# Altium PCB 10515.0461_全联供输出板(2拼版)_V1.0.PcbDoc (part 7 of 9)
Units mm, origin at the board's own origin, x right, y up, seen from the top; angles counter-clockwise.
Board outline 283.88 x 134.8 mm, 2 copper layers (Top Layer, Bottom Layer); 298 components, 0 nets, 1264 pads, 970 vias.
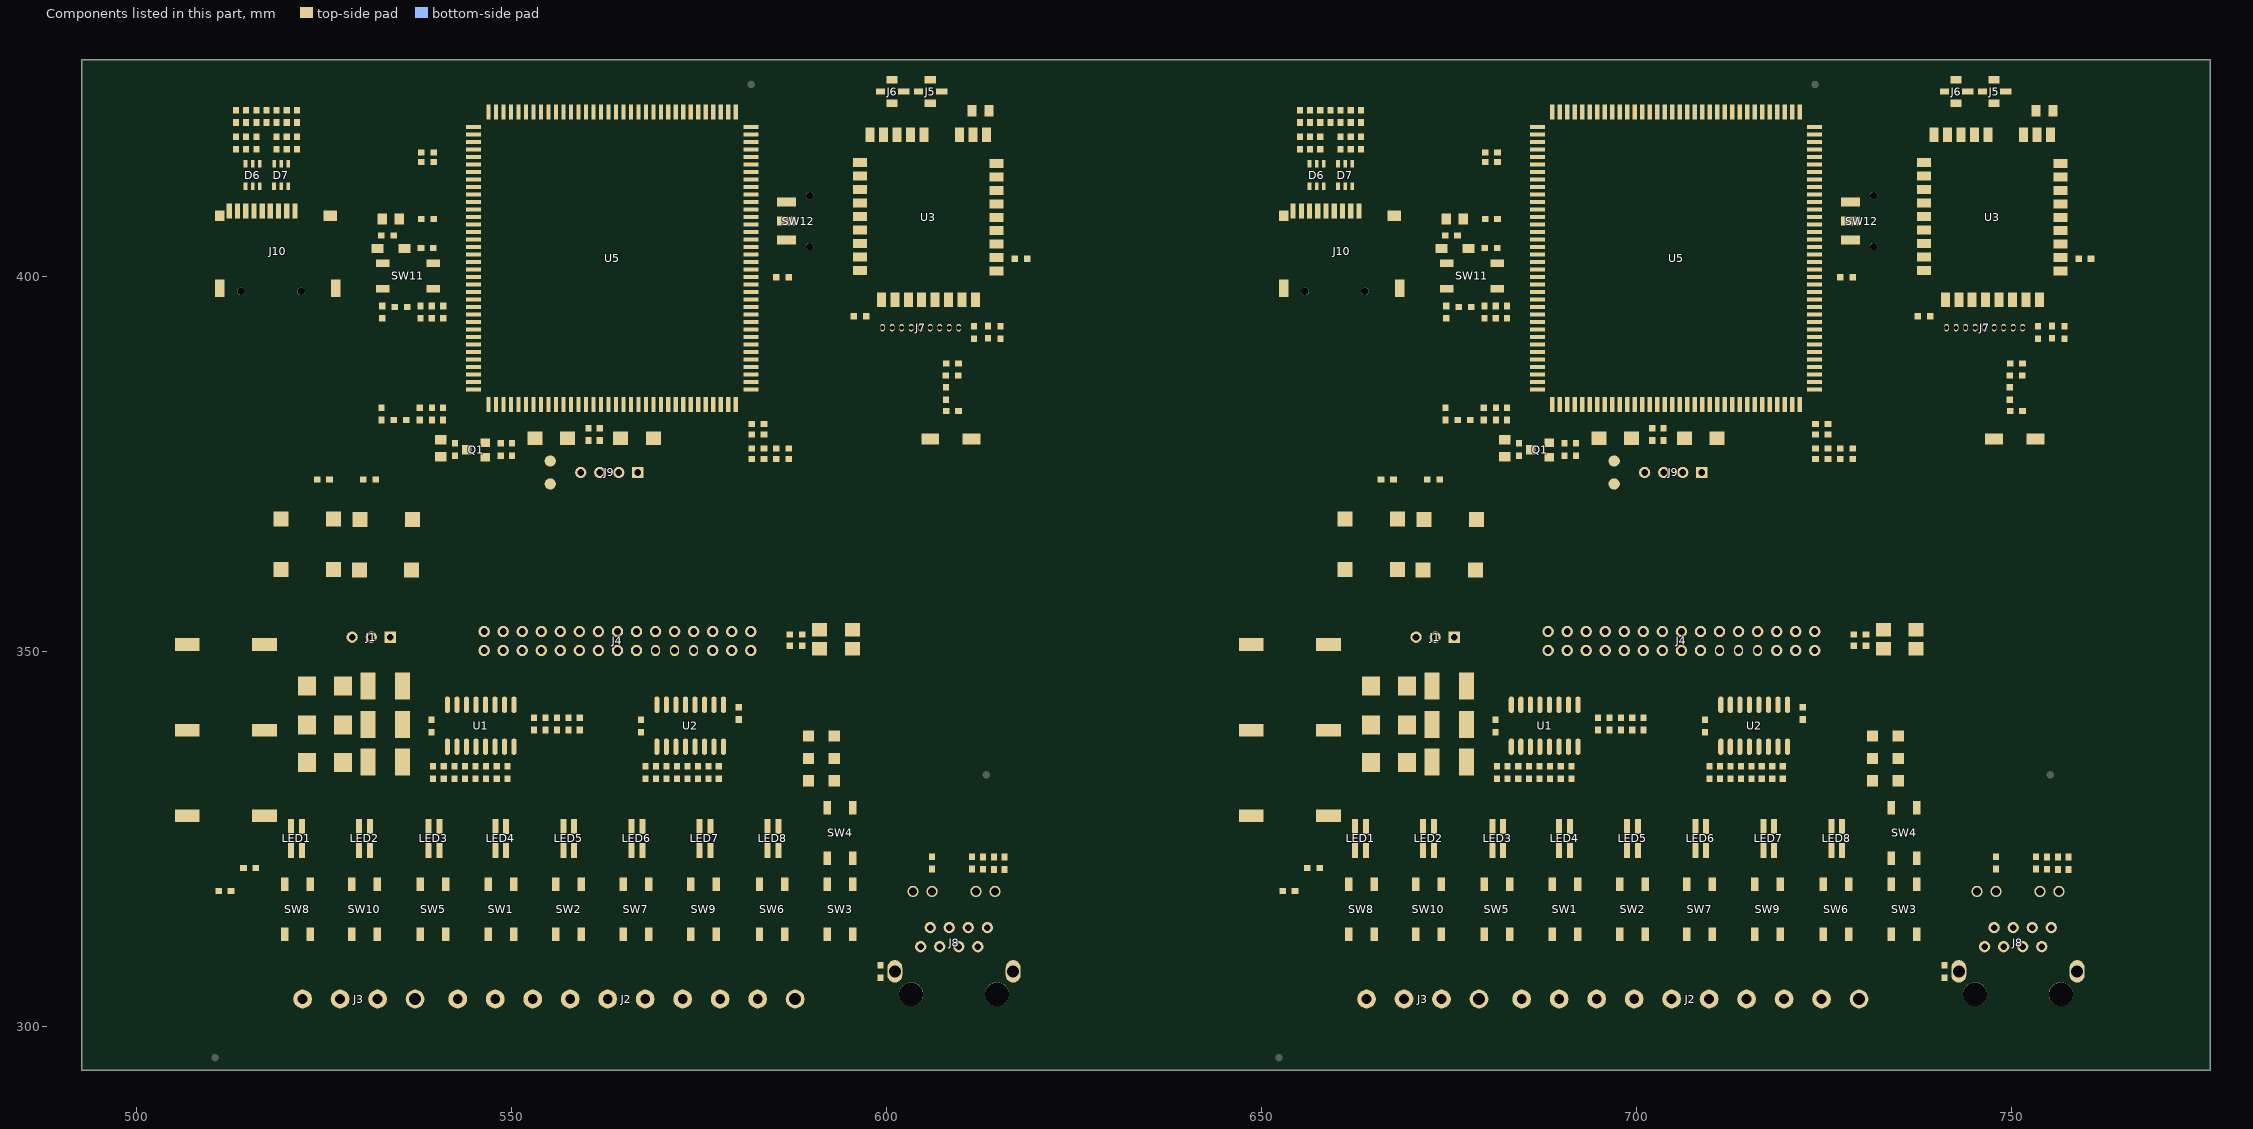
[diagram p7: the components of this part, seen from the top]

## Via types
v1: diameter 0.7, hole 0.4, Top Layer to Bottom Layer, tented both sides, 970 vias

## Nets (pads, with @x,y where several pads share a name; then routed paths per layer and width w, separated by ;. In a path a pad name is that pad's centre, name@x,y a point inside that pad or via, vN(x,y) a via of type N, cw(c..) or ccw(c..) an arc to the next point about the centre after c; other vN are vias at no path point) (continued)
copper on no net: (continued)
  Top Layer w0.8: 752.601,379.719 cw(c751.179,378.297) 753.19,378.297 ; 752.945,378.547 ccw(c752.374,379.13) 753.19,379.13 ; 753.024,377.051 cw(c754.436,377.051) 753.437,378.05 ; 753.393,378.05 cw(c752.81,377.467) 753.634,377.467 ; 753.393,378.544 ccw(c752.81,379.127) 753.634,379.127 ; 753.435,378.547 cw(c754.006,379.13) 753.19,379.13 ; 753.446,379.611 cw(c752.132,378.297) 753.99,378.297 ; 753.532,393.33 754.421,393.33 756.707,393.33 ; 753.634,377.437 cw(c754.5,377.437) 753.887,378.05 ; 753.634,379.157 ccw(c754.5,379.157) 753.887,378.544 ; 755.387,391.717 756.923,391.717 ; 758.34,306.861 ccw(c757.316,305.837) 757.316,307.285 ccw(c757.315,308.734) 758.34,307.709 ; 506.717,328.035 507.907,326.845 509.143,326.845 509.778,326.21 509.778,319.123 510.286,318.615 ; 506.717,328.035 507.826,328.035 508.381,327.48 509.524,327.48 ; 506.717,328.035 v1(510.896,328.035) 510.896,318.005 ; 506.717,328.035 506.717,339.465 506.717,345.501 508.254,347.038 ; 507.746,347.546 508.254,347.038 ; 509.524,327.48 510.286,326.718 510.286,318.615 ; 510.286,302.588 510.286,304.366 ; 510.286,302.588 511.937,300.937 513.715,300.937 510.896,303.756 510.896,318.005 ; 510.286,304.366 510.286,317.395 510.896,318.005 ; 510.286,318.615 510.896,318.005 ; 511.048,406.601 515.594,406.601 525.78,406.601 ; 512.572,305.89 512.572,304.874 513.842,303.604 514.858,303.604 ; 512.572,305.89 514.858,303.604 ; 512.572,305.89 512.572,337.767 ; 512.572,337.767 512.572,338.656 513.969,340.053 ; 512.572,337.767 514.27,339.465 517.017,339.465 ; 513.842,337.132 513.842,324.813 512.572,323.543 513.08,324.051 513.08,337.386 514.477,338.783 ; 513.842,337.132 516.175,339.465 ; 513.969,340.053 518.414,340.053 ; 514.223,308.176 514.223,307.033 514.731,306.525 515.874,306.525 ; 514.223,308.176 515.874,306.525 ; 514.477,338.783 515.493,338.783 516.175,339.465 ; 515.849,320.622 515.849,321.053 ; 515.849,321.053 515.849,325.829 ; 515.849,321.053 516.509,321.713 ; 515.849,325.829 515.849,333.043 516.382,333.576 ; 515.849,325.829 515.849,326.867 517.017,328.035 517.017,334.211 ; 515.874,306.525 538.988,306.525 540.004,305.509 540.004,301.318 540.639,300.683 556.768,300.683 557.777,301.692 ; 516.175,339.465 517.017,339.465 ; 516.175,339.465 517.017,339.465 ; 516.382,333.576 517.017,334.211 ; 516.509,321.713 516.509,326.464 517.779,327.734 517.779,333.957 518.414,334.592 519.049,334.592 ; 517.017,334.211 517.652,334.846 ; 517.017,339.465 517.826,339.465 518.414,340.053 ; 517.017,346.657 517.017,350.895 ; 517.017,350.895 517.779,350.133 517.779,348.054 517.779,347.419 ; 517.017,350.895 518.16,350.895 518.748,351.483 ; 517.017,350.895 523.033,350.895 ; 518.748,351.483 523.621,351.483 523.033,350.895 ; 519.232,360.881 519.232,354.983 519.684,354.531 ; 519.232,360.881 519.232,367.612 ; 519.232,367.612 519.303,367.612 519.938,368.247 521.589,368.247 ; 519.232,367.612 521.716,367.612 524.027,369.923 524.027,372.919 ; 519.684,354.531 520.113,354.102 549.91,354.102 ; 521.462,358.087 521.462,356.563 v1@521.97,356.563 ; v1@521.97,356.563 528.574,356.563 530.225,358.214 530.225,361.383 ; 523.033,350.895 527.732,350.895 528.701,351.864 ; 524.027,372.919 523.494,373.452 523.494,384.757 524.027,385.29 ; 524.027,372.919 524.027,385.29 ; 524.027,385.29 525.018,386.281 528.193,386.281 528.828,386.916 ; 525.678,372.919 525.678,373.225 526.161,373.708 ; 525.678,372.919 525.678,382.369 ; 525.678,372.919 525.678,368.166 526.232,367.612 ; 525.678,382.369 526.669,383.36 ; 526.232,367.612 526.232,360.881 526.232,361.206 526.923,361.897 ; 526.669,383.36 529.082,383.36 530.352,384.63 ; 528.828,386.916 528.828,394.917 529.946,396.035 532.715,396.035 ; 529.773,367.535 529.773,372.442 530.2,372.869 ; 529.773,367.535 530.2,367.962 530.2,372.869 ; 529.773,367.535 529.646,367.408 529.646,360.804 530.225,361.383 ; 530.2,372.869 530.2,373.225 529.59,373.835 529.59,381.836 530.225,382.471 531.114,382.471 ; 530.2,372.869 530.2,381.557 531.114,382.471 ; 531.114,382.471 532.638,382.471 533.4,382.471 ; 531.851,372.869 537.464,372.869 ; 531.851,372.869 531.851,373.581 ; 531.851,372.869 531.851,372.336 532.384,371.803 532.384,369.898 534.162,368.12 ; 531.851,372.869 531.851,369.669 533.985,367.535 536.773,367.535 ; 534.162,368.12 536.188,368.12 536.773,367.535 ; 537.464,372.869 539.717,370.616 540.683,370.616 ; 537.464,372.869 538.43,372.869 540.683,370.616 ; 537.718,340.434 537.718,345.768 ; 537.718,345.768 v1@537.718,347.165 ; 537.718,345.768 537.718,346.149 539.623,348.054 v1(539.623,348.435) v1@538.988,348.435 ; v1@537.718,347.165 v1@538.988,348.435 ; 540.683,370.616 553.847,370.616 ; 549.91,354.102 549.91,354.15 550.672,354.15 551.386,353.436 551.386,352.626 549.91,354.102 ; 551.18,355.674 552.196,355.674 ; 551.18,355.674 553.926,352.928 ; 552.196,355.674 553.926,353.944 ; 552.196,355.674 553.212,355.674 ; 553.212,355.674 553.926,354.96 553.926,353.944 ; 553.847,370.616 565.023,370.616 ; 553.926,352.928 553.926,353.944 ; 565.023,370.616 565.912,370.616 566.801,371.505 566.801,373.835 ; 565.023,370.616 566.801,372.394 566.801,373.835 ; 565.658,375.994 566.928,375.994 ; 566.554,373.588 cw(c565.956,372.99) 566.801,372.99 ; 566.554,373.588 cw(c565.956,372.99) 566.801,372.99 ; 566.801,372.99 cw(c567.646,372.99) 567.048,373.588 ; 566.801,372.99 cw(c567.646,372.99) 567.048,373.588 ; 566.801,373.835 586.359,373.835 ; 566.928,375.994 v1(568.833,375.994) ; v1(568.833,375.994) 568.858,375.994 568.858,378.407 v1@568.858,376.908 ; 568.858,377.2 ccw(c567.651,377.2) 568.504,378.053 cw(c567.651,377.2) 568.858,377.2 ; 568.858,377.2 cw(c570.065,377.2) 569.212,378.053 ccw(c570.065,377.2) 568.858,377.2 ; 586.359,373.835 v1(589.026,373.835) 589.026,374.343 v1(588.962,374.407) ; 586.359,373.835 586.93,374.407 ; 586.93,374.407 v1(588.962,374.407) ; v1(601.091,373.835) 601.599,374.343 ; v1(601.091,373.835) 605.155,373.835 605.8,374.48 605.8,378.297 ; 601.599,374.343 604.647,374.343 605.155,374.851 605.155,377.652 605.8,378.297 ; v1@601.726,371.93 609.092,371.93 ; v1@601.726,371.93 v1(601.218,371.422) 610.489,371.422 611.734,372.667 611.734,379.423 609.575,381.582 609.575,382.013 ; 605.155,379.244 607.924,382.013 ; 605.8,378.297 607.924,380.421 v1(607.924,380.693) ; v1(607.924,380.693) 607.924,382.013 ; 609.092,371.93 610.108,371.93 611.124,372.946 611.124,378.131 611.29,378.297 ; 609.575,382.013 609.575,380.012 611.29,378.297 ; 611.29,378.297 611.29,379.13 ; 648.617,328.035 649.807,326.845 651.043,326.845 651.678,326.21 651.678,319.123 652.186,318.615 ; 648.617,328.035 649.726,328.035 650.281,327.48 651.424,327.48 ; 648.617,328.035 v1(652.796,328.035) 652.796,318.005 ; 648.617,328.035 648.617,339.465 648.617,345.501 650.154,347.038 ; 649.646,347.546 650.154,347.038 ; 651.424,327.48 652.186,326.718 652.186,318.615 ; 652.186,302.588 652.186,304.366 ; 652.186,302.588 653.837,300.937 655.615,300.937 652.796,303.756 652.796,318.005 ; 652.186,304.366 652.186,317.395 652.796,318.005 ; 652.186,318.615 652.796,318.005 ; 652.948,406.601 657.494,406.601 667.68,406.601 ; 654.472,305.89 654.472,304.874 655.742,303.604 656.758,303.604 ; 654.472,305.89 656.758,303.604 ; 654.472,305.89 654.472,337.767 ; 654.472,337.767 654.472,338.656 655.869,340.053 ; 654.472,337.767 656.17,339.465 658.917,339.465 ; 655.742,337.132 655.742,324.813 654.472,323.543 654.98,324.051 654.98,337.386 656.377,338.783 ; 655.742,337.132 658.075,339.465 ; 655.869,340.053 660.314,340.053 ; 656.123,308.176 656.123,307.033 656.631,306.525 657.774,306.525 ; 656.123,308.176 657.774,306.525 ; 656.377,338.783 657.393,338.783 658.075,339.465 ; 657.749,320.622 657.749,321.053 ; 657.749,321.053 657.749,325.829 ; 657.749,321.053 658.409,321.713 ; 657.749,325.829 657.749,333.043 658.282,333.576 ; 657.749,325.829 657.749,326.867 658.917,328.035 658.917,334.211 ; 657.774,306.525 680.888,306.525 681.904,305.509 681.904,301.318 682.539,300.683 698.668,300.683 699.677,301.692 ; 658.075,339.465 658.917,339.465 ; 658.075,339.465 658.917,339.465 ; 658.282,333.576 658.917,334.211 ; 658.409,321.713 658.409,326.464 659.679,327.734 659.679,333.957 660.314,334.592 660.949,334.592 ; 658.917,334.211 659.552,334.846 ; 658.917,339.465 659.726,339.465 660.314,340.053 ; 658.917,346.657 658.917,350.895 ; 658.917,350.895 659.679,350.133 659.679,348.054 659.679,347.419 ; 658.917,350.895 660.06,350.895 660.648,351.483 ; 658.917,350.895 664.933,350.895 ; 660.648,351.483 665.521,351.483 664.933,350.895 ; 661.132,360.881 661.132,354.983 661.584,354.531 ; 661.132,360.881 661.132,367.612 ; 661.132,367.612 661.203,367.612 661.838,368.247 663.489,368.247 ; 661.132,367.612 663.616,367.612 665.927,369.923 665.927,372.919 ; 661.584,354.531 662.013,354.102 691.81,354.102 ; 663.362,358.087 663.362,356.563 v1@663.87,356.563 ; v1@663.87,356.563 670.474,356.563 672.125,358.214 672.125,361.383 ; 664.933,350.895 669.632,350.895 670.601,351.864 ; 665.927,372.919 665.394,373.452 665.394,384.757 665.927,385.29 ; 665.927,372.919 665.927,385.29 ; 665.927,385.29 666.918,386.281 670.093,386.281 670.728,386.916 ; 667.578,372.919 667.578,373.225 668.061,373.708 ; 667.578,372.919 667.578,382.369 ; 667.578,372.919 667.578,368.166 668.132,367.612 ; 667.578,382.369 668.569,383.36 ; 668.132,367.612 668.132,360.881 668.132,361.206 668.823,361.897 ; 668.569,383.36 670.982,383.36 672.252,384.63 ; 670.728,386.916 670.728,394.917 671.846,396.035 674.615,396.035 ; 671.673,367.535 671.673,372.442 672.1,372.869 ; 671.673,367.535 672.1,367.962 672.1,372.869 ; 671.673,367.535 671.546,367.408 671.546,360.804 672.125,361.383 ; 672.1,372.869 672.1,373.225 671.49,373.835 671.49,381.836 672.125,382.471 673.014,382.471 ; 672.1,372.869 672.1,381.557 673.014,382.471 ; 673.014,382.471 674.538,382.471 675.3,382.471 ; 673.751,372.869 679.364,372.869 ; 673.751,372.869 673.751,373.581 ; 673.751,372.869 673.751,372.336 674.284,371.803 674.284,369.898 676.062,368.12 ; 673.751,372.869 673.751,369.669 675.885,367.535 678.673,367.535 ; 676.062,368.12 678.088,368.12 678.673,367.535 ; 679.364,372.869 681.617,370.616 682.583,370.616 ; 679.364,372.869 680.33,372.869 682.583,370.616 ; 679.618,340.434 679.618,345.768 ; 679.618,345.768 v1@679.618,347.165 ; 679.618,345.768 679.618,346.149 681.523,348.054 v1(681.523,348.435) v1@680.888,348.435 ; v1@679.618,347.165 v1@680.888,348.435 ; 682.583,370.616 695.747,370.616 ; 691.81,354.102 691.81,354.15 692.572,354.15 693.286,353.436 693.286,352.626 691.81,354.102 ; 693.08,355.674 694.096,355.674 ; 693.08,355.674 695.826,352.928 ; 694.096,355.674 695.826,353.944 ; 694.096,355.674 695.112,355.674 ; 695.112,355.674 695.826,354.96 695.826,353.944 ; 695.747,370.616 706.923,370.616 ; 695.826,352.928 695.826,353.944 ; 706.923,370.616 707.812,370.616 708.701,371.505 708.701,373.835 ; 706.923,370.616 708.701,372.394 708.701,373.835 ; 707.558,375.994 708.828,375.994 ; 708.454,373.588 cw(c707.856,372.99) 708.701,372.99 ; 708.454,373.588 cw(c707.856,372.99) 708.701,372.99 ; 708.701,372.99 cw(c709.546,372.99) 708.948,373.588 ; 708.701,372.99 cw(c709.546,372.99) 708.948,373.588 ; 708.701,373.835 728.259,373.835 ; 708.828,375.994 v1(710.733,375.994) ; v1(710.733,375.994) 710.758,375.994 710.758,378.407 v1@710.758,376.908 ; 710.758,377.2 ccw(c709.551,377.2) 710.404,378.053 cw(c709.551,377.2) 710.758,377.2 ; 710.758,377.2 cw(c711.965,377.2) 711.112,378.053 ccw(c711.965,377.2) 710.758,377.2 ; 728.259,373.835 v1(730.926,373.835) 730.926,374.343 v1(730.862,374.407) ; 728.259,373.835 728.83,374.407 ; 728.83,374.407 v1(730.862,374.407) ; v1(742.991,373.835) 743.499,374.343 ; v1(742.991,373.835) 747.055,373.835 747.7,374.48 747.7,378.297 ; 743.499,374.343 746.547,374.343 747.055,374.851 747.055,377.652 747.7,378.297 ; v1@743.626,371.93 750.992,371.93 ; v1@743.626,371.93 v1(743.118,371.422) 752.389,371.422 753.634,372.667 753.634,379.423 751.475,381.582 751.475,382.013 ; 747.055,379.244 749.824,382.013 ; 747.7,378.297 749.824,380.421 v1(749.824,380.693) ; v1(749.824,380.693) 749.824,382.013 ; 750.992,371.93 752.008,371.93 753.024,372.946 753.024,378.131 753.19,378.297 ; 751.475,382.013 751.475,380.012 753.19,378.297 ; 753.19,378.297 753.19,379.13 ; 515.849,326.059 cw(c518.193,326.059) 516.535,327.717 ccw(c518.193,326.059) 515.849,326.059 ; 537.718,345.633 cw(c539.141,345.633) 538.193,346.694 ccw(c539.141,345.633) 537.718,345.633 ; 601.542,374.286 cw(c602.107,373.721) 602.107,374.52 ccw(c602.107,373.721) 601.542,374.286 ; 657.749,326.059 cw(c660.093,326.059) 658.435,327.717 ccw(c660.093,326.059) 657.749,326.059 ; 679.618,345.633 cw(c681.041,345.633) 680.093,346.694 ccw(c681.041,345.633) 679.618,345.633 ; 743.442,374.286 cw(c744.007,373.721) 744.007,374.52 ccw(c744.007,373.721) 743.442,374.286
  Top Layer w1: 520.573,323.416 529.644,323.416 547.787,323.416 548.894,323.416 ; v1(556.006,323.416) 585.216,323.416 ; 662.473,323.416 671.544,323.416 689.687,323.416 690.794,323.416 ; v1(697.906,323.416) 727.116,323.416
  Top Layer w1.5: 506.17,351.277 ccw(c506.839,351.087) 506.347,350.596 ; 506.717,328.035 506.717,350.895 506.717,350.226 508.889,348.054 511.302,348.054 511.429,347.927 v1(511.429,347.038) 508.508,347.038 506.971,345.501 506.717,345.501 ; 506.717,347.223 cw(c508.831,347.223) 507.336,348.718 ; 506.717,347.805 cw(c509.265,347.805) 507.463,349.607 ; 506.717,349.647 ccw(c508.831,349.647) 507.336,348.152 ; 506.717,350.843 ccw(c509.265,350.843) 507.463,349.041 ; 507.613,350.868 ccw(c509.655,350.289) 508.154,348.789 ; 508.479,347.321 cw(c510.249,345.551) v1@510.249,348.054 ; v1@509.18,348.054 cw(c509.18,345.551) 510.95,347.321 ; 509.942,348.054 cw(c509.942,345.551) 511.712,347.321 ; 510.618,348.651 cw(c509.765,347.223) v1@511.429,347.223 ; 510.696,348.591 cw(c508.926,346.821) v1@511.429,346.821 ; 510.95,346.755 ccw(c509.793,347.912) v1@511.429,347.912 ; 521.56,356.973 cw(c523.33,355.203) v1@523.33,357.706 ; v1(521.97,357.706) 524.51,357.706 ; 522.567,357.706 cw(c522.567,355.636) 524.031,357.1 ; 522.576,356.973 cw(c524.346,355.203) v1@524.346,357.706 ; 526.232,360.881 526.232,358.539 525.399,357.706 524.51,357.706 ; 529.646,360.804 529.646,358.905 528.447,357.706 524.51,357.706 ; 535.272,345.369 535.272,349.291 538.607,352.626 546.306,352.626 ; 535.399,335.481 535.399,345.369 ; 542.904,351.483 cw(c542.904,346.684) 546.298,350.078 ; 543.518,351.483 ccw(c543.518,355.414) 546.298,352.634 ; 545.444,351.483 cw(c545.444,346.684) 548.838,350.078 ; 546.058,351.483 ccw(c546.058,355.414) 548.838,352.634 ; 546.316,352.633 ccw(c548.465,354.066) 548.465,351.483 ; 546.317,350.081 cw(c548.465,349.136) 548.465,351.483 ; 551.386,350.086 551.386,352.626 ; 553.926,350.086 553.926,352.626 ; 556.476,350.079 cw(c559.006,348.211) 559.006,351.356 ; 556.476,352.633 ccw(c559.006,354.501) 559.006,351.356 ; 558.996,350.079 ccw(c556.466,348.211) 556.466,351.356 ; 558.996,352.633 cw(c556.466,354.501) 556.466,351.356 ; 648.07,351.277 ccw(c648.739,351.087) 648.247,350.596 ; 648.617,328.035 648.617,350.895 648.617,350.226 650.789,348.054 653.202,348.054 653.329,347.927 v1(653.329,347.038) 650.408,347.038 648.871,345.501 648.617,345.501 ; 648.617,347.223 cw(c650.731,347.223) 649.236,348.718 ; 648.617,347.805 cw(c651.165,347.805) 649.363,349.607 ; 648.617,349.647 ccw(c650.731,349.647) 649.236,348.152 ; 648.617,350.843 ccw(c651.165,350.843) 649.363,349.041 ; 649.513,350.868 ccw(c651.555,350.289) 650.054,348.789 ; 650.379,347.321 cw(c652.149,345.551) v1@652.149,348.054 ; v1@651.08,348.054 cw(c651.08,345.551) 652.85,347.321 ; 651.842,348.054 cw(c651.842,345.551) 653.612,347.321 ; 652.518,348.651 cw(c651.665,347.223) v1@653.329,347.223 ; 652.596,348.591 cw(c650.826,346.821) v1@653.329,346.821 ; 652.85,346.755 ccw(c651.693,347.912) v1@653.329,347.912 ; 663.46,356.973 cw(c665.23,355.203) v1@665.23,357.706 ; v1(663.87,357.706) 666.41,357.706 ; 664.467,357.706 cw(c664.467,355.636) 665.931,357.1 ; 664.476,356.973 cw(c666.246,355.203) v1@666.246,357.706 ; 668.132,360.881 668.132,358.539 667.299,357.706 666.41,357.706 ; 671.546,360.804 671.546,358.905 670.347,357.706 666.41,357.706 ; 677.172,345.369 677.172,349.291 680.507,352.626 688.206,352.626 ; 677.299,335.481 677.299,345.369 ; 684.804,351.483 cw(c684.804,346.684) 688.198,350.078 ; 685.418,351.483 ccw(c685.418,355.414) 688.198,352.634 ; 687.344,351.483 cw(c687.344,346.684) 690.738,350.078 ; 687.958,351.483 ccw(c687.958,355.414) 690.738,352.634 ; 688.216,352.633 ccw(c690.365,354.066) 690.365,351.483 ; 688.217,350.081 cw(c690.365,349.136) 690.365,351.483 ; 693.286,350.086 693.286,352.626 ; 695.826,350.086 695.826,352.626 ; 698.376,350.079 cw(c700.906,348.211) 700.906,351.356 ; 698.376,352.633 ccw(c700.906,354.501) 700.906,351.356 ; 700.896,350.079 ccw(c698.366,348.211) 698.366,351.356 ccw(c698.366,354.501) 700.896,352.633 ; 546.306,350.086 546.306,352.626 ; 546.306,350.086 548.846,350.086 548.846,352.626 546.306,352.626 ; 546.306,350.086 536.067,350.086 537.464,351.483 548.465,351.483 ; 556.466,351.356 556.466,350.086 559.006,350.086 559.006,352.626 556.514,352.626 556.466,352.578 556.466,351.356 ; 556.466,351.356 559.006,351.356 ; 688.206,350.086 688.206,352.626 ; 688.206,350.086 690.746,350.086 690.746,352.626 688.206,352.626 ; 688.206,350.086 677.967,350.086 679.364,351.483 690.365,351.483 ; 698.366,351.356 698.366,350.086 700.906,350.086 700.906,352.626 698.414,352.626 698.366,352.578 698.366,351.356 ; 698.366,351.356 700.906,351.356
  Bottom Layer w0.3: v1@513.066,419.414 cw(c512.724,419.072) 513.207,419.072 cw(c513.69,419.072) v1@513.348,419.414 ; v1(513.207,419.555) 513.207,415.872 514.477,414.602 v1@514.477,412.951 ; v1(513.461,425.397) v1(517.144,425.397) ; v1@513.602,425.256 cw(c513.944,424.914) 513.944,425.397 cw(c513.944,425.88) v1@513.602,425.538 ; v1@514.209,413.092 ccw(c513.561,413.74) 514.477,413.74 ; v1@514.214,416.008 ccw(c513.373,416.849) 514.562,416.849 ; v1@514.42,419.414 cw(c514.079,419.072) 514.562,419.072 cw(c515.045,419.072) v1@514.703,419.414 ; v1@514.482,415.867 514.562,415.947 v1(514.562,419.555) ; v1@514.971,406.742 ccw(c514.629,407.084) 515.112,407.084 ccw(c515.595,407.084) v1@515.253,406.742 ; v1(515.112,406.601) 515.112,412.631 515.432,412.951 ; v1@515.186,415.726 cw(c514.591,415.131) 515.432,415.131 ; v1@515.432,415.938 515.432,412.951 ; v1@515.916,419.355 cw(c515.916,418.872) 516.258,419.214 cw(c516.599,419.555) v1@516.116,419.555 ; v1(515.916,419.555) 516.213,419.259 516.382,419.089 v1@516.382,415.872 ; v1@515.94,410.604 v1@519.237,410.604 ; v1@516.158,416.008 ccw(c515.616,416.55) 516.382,416.55 ; v1@516.208,410.463 cw(c516.55,410.121) 516.55,410.604 cw(c516.55,411.087) v1@516.208,410.745 ; v1@517.003,425.256 ccw(c516.661,424.914) 516.661,425.397 ccw(c516.661,425.88) v1@517.003,425.538 ; v1@517.13,416.008 ccw(c516.788,416.35) 517.271,416.35 ccw(c517.754,416.35) v1@517.412,416.008 ; v1@517.13,417.763 cw(c516.788,417.421) 517.271,417.421 cw(c517.754,417.421) v1@517.412,417.763 ; v1@517.271,415.872 v1(517.271,417.904) ; v1@517.638,410.463 ccw(c517.296,410.121) 517.296,410.604 ccw(c517.296,411.087) v1@517.638,410.745 ; v1@517.92,410.463 cw(c518.262,410.121) 518.262,410.604 cw(c518.262,411.087) v1@517.92,410.745 ; 518.08,412.951 ccw(c518.08,414.301) v1@519.035,413.346 ; v1@518.146,413.981 ccw(c517.804,414.323) 518.287,414.323 ccw(c518.77,414.323) v1@518.428,413.981 ; v1(518.287,413.84) 518.287,419.216 v1(518.626,419.555) ; 518.287,418.255 cw(c519.926,418.255) v1@518.767,419.414 ; 518.287,418.979 cw(c519.202,418.979) v1@518.555,419.626 ; v1@518.484,423.549 ccw(c518.143,423.89) 518.626,423.89 ccw(c519.109,423.89) v1@518.767,423.549 ; v1(518.626,423.407) 518.626,424.593 v1(519.049,425.016) ; 518.661,410.604 cw(c518.661,409.896) v1@519.162,410.397 ; 518.804,412.951 ccw(c518.804,413.577) v1@519.247,413.134 ; v1@518.849,425.016 cw(c518.366,425.016) 518.708,424.675 cw(c519.049,424.333) v1@519.049,424.816 ; 518.922,412.951 515.432,412.951 ; v1@519.035,413.064 cw(c518.693,412.722) 519.176,412.722 cw(c519.659,412.722) v1@519.317,413.064 ; v1(519.176,413.205) 519.176,411.935 519.557,411.554 529.59,411.554 530.225,410.919 ; v1(519.303,410.538) v1(521.97,410.538) ; v1@519.444,410.397 cw(c519.786,410.055) 519.786,410.538 cw(c519.786,411.021) v1@519.444,410.679 ; v1@519.839,419.414 cw(c519.497,419.072) 519.98,419.072 cw(c520.463,419.072) v1@520.122,419.414 ; v1@519.839,423.591 ccw(c519.497,423.933) 519.98,423.933 ccw(c520.463,423.933) v1@520.122,423.591 ; 519.98,416.866 ccw(c521.186,416.866) v1@520.333,416.013 ; v1(519.98,419.555) 519.98,416.084 v1(520.192,415.872) ; v1(519.98,423.45) 519.98,427.09 v1(520.573,427.683) ; v1@520.051,413.727 ccw(c519.709,414.069) 520.192,414.069 ccw(c520.675,414.069) v1@520.333,413.727 ; v1(520.192,413.586) 520.192,414.729 521.335,415.872 v1(521.335,419.555) ; v1@520.373,427.683 cw(c519.89,427.683) 520.232,427.342 cw(c520.573,427) v1@520.573,427.483 ; v1@521.194,419.414 cw(c520.852,419.072) 521.335,419.072 cw(c521.818,419.072) v1@521.476,419.414 ; v1@521.194,423.633 ccw(c520.852,423.975) 521.335,423.975 ccw(c521.818,423.975) v1@521.476,423.633 ; v1(521.335,423.492) 521.335,427.683 v1(521.97,428.318) ; v1@521.77,428.318 cw(c521.287,428.318) 521.629,427.977 cw(c521.97,427.635) v1@521.97,428.118 ; v1@521.829,410.397 ccw(c521.487,410.055) 521.487,410.538 ccw(c521.487,411.021) v1@521.829,410.679 ; v1(526.923,312.243) v1(533.4,312.243) ; v1@527.064,312.101 cw(c527.406,311.76) 527.406,312.243 cw(c527.406,312.726) v1@527.064,312.384 ; v1(528.633,320.427) 529.209,321.003 v1(533.146,321.003) ; v1@528.633,320.627 ccw(c528.633,321.11) 528.974,320.768 ccw(c529.316,320.427) v1@528.833,320.427 ; v1@533.005,320.862 ccw(c532.663,320.52) 532.663,321.003 ccw(c532.663,321.486) v1@533.005,321.144 ; v1@533.259,312.101 ccw(c532.917,311.76) 532.917,312.243 ccw(c532.917,312.726) v1@533.259,312.384 ; 533.654,348.133 533.781,348.26 ; v1(537.845,314.272) v1(556.895,314.272) ; v1@537.986,314.131 cw(c538.328,313.789) 538.328,314.272 cw(c538.328,314.755) v1@537.986,314.413 ; v1(546.481,344.371) 546.481,343.99 ; v1(548.259,345.26) v1(575.691,345.26) ; v1@548.4,345.119 cw(c548.742,344.777) 548.742,345.26 cw(c548.742,345.743) v1@548.4,345.401 ; v1@554.341,335.368 ccw(c553.999,335.71) 554.482,335.71 ccw(c554.965,335.71) v1@554.623,335.368 ; v1@554.341,338.134 cw(c553.999,337.792) 554.482,337.792 cw(c554.965,337.792) v1@554.623,338.134 ; v1(554.482,335.227) v1(554.482,338.275) ; v1@555.865,334.606 ccw(c555.523,334.948) 556.006,334.948 ccw(c556.489,334.948) v1@556.147,334.606 ; v1@555.865,338.134 cw(c555.523,337.792) 556.006,337.792 cw(c556.489,337.792) v1@556.147,338.134 ; v1(556.006,334.465) v1(556.006,338.275) ; v1@556.754,314.131 ccw(c556.412,313.789) 556.412,314.272 ccw(c556.412,314.755) v1@556.754,314.413 ; v1@557.389,333.717 ccw(c557.047,334.059) 557.53,334.059 ccw(c558.013,334.059) v1@557.671,333.717 ; v1@557.389,338.134 cw(c557.047,337.792) 557.53,337.792 cw(c558.013,337.792) v1@557.671,338.134 ; v1(557.53,333.576) v1(557.53,338.275) ; v1@558.913,332.955 ccw(c558.571,333.297) 559.054,333.297 ccw(c559.537,333.297) v1@559.195,332.955 ; v1@558.913,338.134 cw(c558.571,337.792) 559.054,337.792 cw(c559.537,337.792) v1@559.195,338.134 ; v1(559.054,332.814) v1(559.054,338.275) ; v1@562.596,426.272 cw(c561.945,425.621) 562.865,425.621 ; v1@562.724,385.024 ccw(c562.382,385.366) 562.865,385.366 ccw(c563.348,385.366) v1@563.006,385.024 ; v1(562.865,384.883) 562.865,420.063 ; 562.865,420.317 562.865,420.063 ; v1@562.865,426.285 562.865,420.063 ; 567.144,304.504 ccw(c566.286,305.723) 567.777,305.723 ; 567.317,304.258 ccw(c566.693,305.145) 567.777,305.145 ccw(c568.861,305.145) 568.237,304.258 ; 567.777,303.604 567.777,305.723 ; 568.41,304.504 cw(c569.268,305.723) 567.777,305.723 ; v1@574.221,344.244 cw(c573.738,344.244) 574.08,343.903 cw(c574.421,343.561) v1@574.421,344.044 ; v1@574.35,344.315 cw(c574.793,343.872) 574.793,344.498 ; 574.394,306.144 cw(c574.394,305.228) v1@575.042,305.876 ; v1@574.562,344.103 cw(c575.517,343.148) 575.517,344.498 ; v1@575.324,305.876 cw(c575.972,305.228) 575.972,306.144 ; v1@575.55,345.119 ccw(c575.208,344.777) 575.208,345.26 ccw(c575.208,345.743) v1@575.55,345.401 ; 577.037,304.418 ccw(c575.518,306.09) 577.777,306.09 ; 577.239,304.196 ccw(c576.134,305.412) 577.777,305.412 ccw(c579.42,305.412) 578.315,304.196 ; 577.777,303.604 577.777,306.09 ; 578.517,304.418 cw(c580.036,306.09) 577.777,306.09 ; v1@578.979,344.357 ccw(c578.637,344.015) 578.637,344.498 ccw(c578.637,344.981) v1@578.979,344.639 ; v1(579.12,344.498) 574.675,344.498 v1(574.421,344.244) 573.913,343.736 546.735,343.736 546.481,343.99 ; 580.176,306.144 cw(c580.176,305.228) v1@580.824,305.876 ; v1@581.107,305.876 cw(c581.755,305.228) 581.755,306.144 ; v1(584.454,375.613) 585.978,375.613 586.532,376.167 586.532,391.661 587.248,392.377 v1(593.725,392.377) ; v1(584.454,377.01) 585.216,377.01 585.978,377.772 585.978,390.726 585.978,392.504 586.613,393.139 v1(594.614,393.139) ; v1@584.595,375.472 cw(c584.937,375.13) 584.937,375.613 cw(c584.937,376.096) v1@584.595,375.754 ; v1@584.595,376.869 cw(c584.937,376.527) 584.937,377.01 cw(c584.937,377.493) v1@584.595,377.151 ; 587.138,304.499 ccw(c586.249,305.742) 587.777,305.742 ; 587.312,304.255 ccw(c586.666,305.159) 587.777,305.159 ccw(c588.888,305.159) 588.242,304.255 ; v1@587.742,378.04 ccw(c587.4,378.382) 587.883,378.382 ccw(c588.366,378.382) v1@588.024,378.04 ; 587.777,303.604 587.777,305.742 ; v1(587.883,377.899) 587.883,390.472 588.137,390.726 v1(588.772,390.726) ; 588.416,304.499 cw(c589.305,305.742) 587.777,305.742 ; v1@588.631,390.585 ccw(c588.289,390.243) 588.289,390.726 ccw(c588.289,391.209) v1@588.631,390.867 ; v1@589.52,350.862 ccw(c589.178,351.204) 589.661,351.204 ccw(c590.144,351.204) v1@589.802,350.862 ; v1@589.52,355.66 cw(c589.178,355.318) 589.661,355.318 cw(c590.144,355.318) v1@589.802,355.66 ; v1(589.661,350.721) v1(589.661,355.801) ; v1@593.584,392.236 ccw(c593.242,391.894) 593.242,392.377 ccw(c593.242,392.86) v1@593.584,392.518 ; v1@594.473,392.998 ccw(c594.131,392.656) 594.131,393.139 ccw(c594.131,393.622) v1@594.473,393.28 ; v1(606.552,325.575) 606.552,325.194 ; 607.064,310.585 608.211,311.732 609.141,311.732 610.534,313.125 610.874,313.125 ; 607.064,311.185 ccw(c607.064,312.634) 608.088,311.609 ccw(c609.113,310.585) 607.664,310.585 ; v1@607.427,339.559 ccw(c607.085,339.901) 607.568,339.901 ccw(c608.051,339.901) v1@607.709,339.559 ; v1@607.427,341.436 cw(c607.085,341.094) 607.568,341.094 cw(c608.051,341.094) v1@607.709,341.436 ; v1(607.568,339.418) v1(607.568,341.577) ; 607.91,313.549 ccw(c606.885,314.574) 608.334,314.574 ccw(c609.783,314.574) 608.758,313.549 ; v1@608.189,338.924 ccw(c607.847,339.266) 608.33,339.266 ccw(c608.813,339.266) v1@608.471,338.924 ; v1@608.189,342.071 cw(c607.847,341.729) 608.33,341.729 cw(c608.813,341.729) v1@608.471,342.071 ; v1(608.33,338.783) v1(608.33,342.212) ; 608.334,313.125 608.334,322.404 ; 609.269,311.86 cw(c610.874,310.256) 610.874,312.525 ; 609.781,312.372 cw(c610.874,311.28) 610.874,312.825 ; 610.09,312.681 ccw(c609.646,313.125) 610.274,313.125 ; 610.489,314.054 ccw(c611.803,314.054) 610.874,313.125 ; 610.489,314.779 ccw(c612.528,314.779) 611.086,313.337 ; 610.489,315.503 ccw(c613.252,315.503) 611.298,313.549 ; v1@610.856,324.799 ccw(c610.514,324.457) 610.514,324.94 ccw(c610.514,325.423) v1@610.856,325.081 ; v1(610.997,324.94) 606.806,324.94 606.552,325.194 ; v1@611.178,319.606 cw(c610.695,319.606) 611.037,319.265 cw(c611.378,318.923) v1@611.378,319.406 ; v1(611.378,319.606) 610.489,318.717 610.489,313.51 610.874,313.125 ; v1@654.966,419.414 cw(c654.624,419.072) 655.107,419.072 cw(c655.59,419.072) v1@655.248,419.414 ; v1(655.107,419.555) 655.107,415.872 656.377,414.602 v1@656.377,412.951 ; v1(655.361,425.397) v1(659.044,425.397) ; v1@655.502,425.256 cw(c655.844,424.914) 655.844,425.397 cw(c655.844,425.88) v1@655.502,425.538 ; v1@656.109,413.092 ccw(c655.461,413.74) 656.377,413.74 ; v1@656.114,416.008 ccw(c655.273,416.849) 656.462,416.849 ; v1@656.32,419.414 cw(c655.979,419.072) 656.462,419.072 cw(c656.945,419.072) v1@656.603,419.414 ; v1@656.382,415.867 656.462,415.947 v1(656.462,419.555) ; v1@656.871,406.742 ccw(c656.529,407.084) 657.012,407.084 ccw(c657.495,407.084) v1@657.153,406.742 ; v1(657.012,406.601) 657.012,412.631 657.332,412.951 ; v1@657.086,415.726 cw(c656.491,415.131) 657.332,415.131 ; v1@657.332,415.938 657.332,412.951 ; v1@657.816,419.355 cw(c657.816,418.872) 658.158,419.214 cw(c658.499,419.555) v1@658.016,419.555 ; v1(657.816,419.555) 658.113,419.259 658.282,419.089 v1@658.282,415.872 ; v1@657.84,410.604 v1@661.137,410.604 ; v1@658.058,416.008 ccw(c657.516,416.55) 658.282,416.55 ; v1@658.108,410.463 cw(c658.45,410.121) 658.45,410.604 cw(c658.45,411.087) v1@658.108,410.745 ; v1@658.903,425.256 ccw(c658.561,424.914) 658.561,425.397 ccw(c658.561,425.88) v1@658.903,425.538 ; v1@659.03,416.008 ccw(c658.688,416.35) 659.171,416.35 ccw(c659.654,416.35) v1@659.312,416.008 ; v1@659.03,417.763 cw(c658.688,417.421) 659.171,417.421 cw(c659.654,417.421) v1@659.312,417.763 ; v1@659.171,415.872 v1(659.171,417.904) ; v1@659.538,410.463 ccw(c659.196,410.121) 659.196,410.604 ccw(c659.196,411.087) v1@659.538,410.745 ; v1@659.82,410.463 cw(c660.162,410.121) 660.162,410.604 cw(c660.162,411.087) v1@659.82,410.745 ; 659.98,412.951 ccw(c659.98,414.301) v1@660.935,413.346 ; v1@660.046,413.981 ccw(c659.704,414.323) 660.187,414.323 ccw(c660.67,414.323) v1@660.328,413.981 ; v1(660.187,413.84) 660.187,419.216 v1(660.526,419.555) ; 660.187,418.255 cw(c661.826,418.255) v1@660.667,419.414 ; 660.187,418.979 cw(c661.102,418.979) v1@660.455,419.626 ; v1@660.384,423.549 ccw(c660.043,423.89) 660.526,423.89 ccw(c661.009,423.89) v1@660.667,423.549 ; v1(660.526,423.407) 660.526,424.593 v1(660.949,425.016) ; 660.561,410.604 cw(c660.561,409.896) v1@661.062,410.397 ; 660.704,412.951 ccw(c660.704,413.577) v1@661.147,413.134 ; v1@660.749,425.016 cw(c660.266,425.016) 660.608,424.675 cw(c660.949,424.333) v1@660.949,424.816 ; 660.822,412.951 657.332,412.951 ; v1@660.935,413.064 cw(c660.593,412.722) 661.076,412.722 cw(c661.559,412.722) v1@661.217,413.064 ; v1(661.076,413.205) 661.076,411.935 661.457,411.554 671.49,411.554 672.125,410.919 ; v1(661.203,410.538) v1(663.87,410.538) ; v1@661.344,410.397 cw(c661.686,410.055) 661.686,410.538 cw(c661.686,411.021) v1@661.344,410.679 ; v1@661.739,419.414 cw(c661.397,419.072) 661.88,419.072 cw(c662.363,419.072) v1@662.022,419.414 ; v1@661.739,423.591 ccw(c661.397,423.933) 661.88,423.933 ccw(c662.363,423.933) v1@662.022,423.591 ; 661.88,416.866 ccw(c663.086,416.866) v1@662.233,416.013 ; v1(661.88,419.555) 661.88,416.084 v1(662.092,415.872) ; v1(661.88,423.45) 661.88,427.09 v1(662.473,427.683) ; v1@661.951,413.727 ccw(c661.609,414.069) 662.092,414.069 ccw(c662.575,414.069) v1@662.233,413.727 ; v1(662.092,413.586) 662.092,414.729 663.235,415.872 v1(663.235,419.555) ; v1@662.273,427.683 cw(c661.79,427.683) 662.132,427.342 cw(c662.473,427) v1@662.473,427.483 ; v1@663.094,419.414 cw(c662.752,419.072) 663.235,419.072 cw(c663.718,419.072) v1@663.376,419.414 ; v1@663.094,423.633 ccw(c662.752,423.975) 663.235,423.975 ccw(c663.718,423.975) v1@663.376,423.633 ; v1(663.235,423.492) 663.235,427.683 v1(663.87,428.318) ; v1@663.67,428.318 cw(c663.187,428.318) 663.529,427.977 cw(c663.87,427.635) v1@663.87,428.118 ; v1@663.729,410.397 ccw(c663.387,410.055) 663.387,410.538 ccw(c663.387,411.021) v1@663.729,410.679 ; v1(668.823,312.243) v1(675.3,312.243) ; v1@668.964,312.101 cw(c669.306,311.76) 669.306,312.243 cw(c669.306,312.726) v1@668.964,312.384 ; v1(670.533,320.427) 671.109,321.003 v1(675.046,321.003) ; v1@670.533,320.627 ccw(c670.533,321.11) 670.874,320.768 ccw(c671.216,320.427) v1@670.733,320.427 ; v1@674.905,320.862 ccw(c674.563,320.52) 674.563,321.003 ccw(c674.563,321.486) v1@674.905,321.144 ; v1@675.159,312.101 ccw(c674.817,311.76) 674.817,312.243 ccw(c674.817,312.726) v1@675.159,312.384 ; 675.554,348.133 675.681,348.26 ; v1(679.745,314.272) v1(698.795,314.272) ; v1@679.886,314.131 cw(c680.228,313.789) 680.228,314.272 cw(c680.228,314.755) v1@679.886,314.413 ; v1(688.381,344.371) 688.381,343.99 ; v1(690.159,345.26) v1(717.591,345.26) ; v1@690.3,345.119 cw(c690.642,344.777) 690.642,345.26 cw(c690.642,345.743) v1@690.3,345.401 ; v1@696.241,335.368 ccw(c695.899,335.71) 696.382,335.71 ccw(c696.865,335.71) v1@696.523,335.368 ; v1@696.241,338.134 cw(c695.899,337.792) 696.382,337.792 cw(c696.865,337.792) v1@696.523,338.134 ; v1(696.382,335.227) v1(696.382,338.275) ; v1@697.765,334.606 ccw(c697.423,334.948) 697.906,334.948 ccw(c698.389,334.948) v1@698.047,334.606 ; v1@697.765,338.134 cw(c697.423,337.792) 697.906,337.792 cw(c698.389,337.792) v1@698.047,338.134 ; v1(697.906,334.465) v1(697.906,338.275) ; v1@698.654,314.131 ccw(c698.312,313.789) 698.312,314.272 ccw(c698.312,314.755) v1@698.654,314.413 ; v1@699.289,333.717 ccw(c698.947,334.059) 699.43,334.059 ccw(c699.913,334.059) v1@699.571,333.717 ; v1@699.289,338.134 cw(c698.947,337.792) 699.43,337.792 cw(c699.913,337.792) v1@699.571,338.134 ; v1(699.43,333.576) v1(699.43,338.275) ; v1@700.813,332.955 ccw(c700.471,333.297) 700.954,333.297 ccw(c701.437,333.297) v1@701.095,332.955 ; v1@700.813,338.134 cw(c700.471,337.792) 700.954,337.792 cw(c701.437,337.792) v1@701.095,338.134 ; v1(700.954,332.814) v1(700.954,338.275) ; v1@704.496,426.272 cw(c703.845,425.621) 704.765,425.621 ; v1@704.624,385.024 ccw(c704.282,385.366) 704.765,385.366 ccw(c705.248,385.366) v1@704.906,385.024 ; v1(704.765,384.883) 704.765,420.063 ; 704.765,420.317 704.765,420.063 ; v1@704.765,426.285 704.765,420.063 ; 709.044,304.504 ccw(c708.186,305.723) 709.677,305.723 ; 709.217,304.258 ccw(c708.593,305.145) 709.677,305.145 ccw(c710.761,305.145) 710.137,304.258 ; 709.677,303.604 709.677,305.723 ; 710.31,304.504 cw(c711.168,305.723) 709.677,305.723 ; v1@716.121,344.244 cw(c715.638,344.244) 715.98,343.903 cw(c716.321,343.561) v1@716.321,344.044 ; v1@716.25,344.315 cw(c716.693,343.872) 716.693,344.498 ; 716.294,306.144 cw(c716.294,305.228) v1@716.942,305.876 ; v1@716.462,344.103 cw(c717.417,343.148) 717.417,344.498 ; v1@717.224,305.876 cw(c717.872,305.228) 717.872,306.144 ; v1@717.45,345.119 ccw(c717.108,344.777) 717.108,345.26 ccw(c717.108,345.743) v1@717.45,345.401 ; 718.937,304.418 ccw(c717.418,306.09) 719.677,306.09 ; 719.139,304.196 ccw(c718.034,305.412) 719.677,305.412 ccw(c721.32,305.412) 720.215,304.196 ; 719.677,303.604 719.677,306.09 ; 720.417,304.418 cw(c721.936,306.09) 719.677,306.09 ; v1@720.879,344.357 ccw(c720.537,344.015) 720.537,344.498 ccw(c720.537,344.981) v1@720.879,344.639 ; v1(721.02,344.498) 716.575,344.498 v1(716.321,344.244) 715.813,343.736 688.635,343.736 688.381,343.99 ; 722.076,306.144 cw(c722.076,305.228) v1@722.724,305.876 ; v1@723.007,305.876 cw(c723.655,305.228) 723.655,306.144 ; v1(726.354,375.613) 727.878,375.613 728.432,376.167 728.432,391.661 729.148,392.377 v1(735.625,392.377) ; v1(726.354,377.01) 727.116,377.01 727.878,377.772 727.878,390.726 727.878,392.504 728.513,393.139 v1(736.514,393.139) ; v1@726.495,375.472 cw(c726.837,375.13) 726.837,375.613 cw(c726.837,376.096) v1@726.495,375.754 ; v1@726.495,376.869 cw(c726.837,376.527) 726.837,377.01 cw(c726.837,377.493) v1@726.495,377.151 ; 729.038,304.499 ccw(c728.149,305.742) 729.677,305.742 ; 729.212,304.255 ccw(c728.566,305.159) 729.677,305.159 ccw(c730.788,305.159) 730.142,304.255 ; v1@729.642,378.04 ccw(c729.3,378.382) 729.783,378.382 ccw(c730.266,378.382) v1@729.924,378.04 ; 729.677,303.604 729.677,305.742 ; v1(729.783,377.899) 729.783,390.472 730.037,390.726 v1(730.672,390.726) ; 730.316,304.499 cw(c731.205,305.742) 729.677,305.742 ; v1@730.531,390.585 ccw(c730.189,390.243) 730.189,390.726 ccw(c730.189,391.209) v1@730.531,390.867 ; v1@731.42,350.862 ccw(c731.078,351.204) 731.561,351.204 ccw(c732.044,351.204) v1@731.702,350.862 ; v1@731.42,355.66 cw(c731.078,355.318) 731.561,355.318 cw(c732.044,355.318) v1@731.702,355.66 ; v1(731.561,350.721) v1(731.561,355.801) ; v1@735.484,392.236 ccw(c735.142,391.894) 735.142,392.377 ccw(c735.142,392.86) v1@735.484,392.518 ; v1@736.373,392.998 ccw(c736.031,392.656) 736.031,393.139 ccw(c736.031,393.622) v1@736.373,393.28 ; v1(748.452,325.575) 748.452,325.194 ; 748.964,310.585 750.111,311.732 751.041,311.732 752.434,313.125 752.774,313.125 ; 748.964,311.185 ccw(c748.964,312.634) 749.988,311.609 ccw(c751.013,310.585) 749.564,310.585 ; v1@749.327,339.559 ccw(c748.985,339.901) 749.468,339.901 ccw(c749.951,339.901) v1@749.609,339.559 ; v1@749.327,341.436 cw(c748.985,341.094) 749.468,341.094 cw(c749.951,341.094) v1@749.609,341.436 ; v1(749.468,339.418) v1(749.468,341.577) ; 749.81,313.549 ccw(c748.785,314.574) 750.234,314.574 ccw(c751.682,314.574) 750.658,313.549 ; v1@750.089,338.924 ccw(c749.747,339.266) 750.23,339.266 ccw(c750.713,339.266) v1@750.371,338.924 ; v1@750.089,342.071 cw(c749.747,341.729) 750.23,341.729 cw(c750.713,341.729) v1@750.371,342.071 ; v1(750.23,338.783) v1(750.23,342.212) ; 750.234,313.125 750.234,322.404 ; 751.169,311.86 cw(c752.774,310.256) 752.774,312.525 ; 751.681,312.372 cw(c752.774,311.28) 752.774,312.825 ; 751.99,312.681 ccw(c751.546,313.125) 752.174,313.125 ; 752.389,314.054 ccw(c753.703,314.054) 752.774,313.125 ; 752.389,314.779 ccw(c754.428,314.779) 752.986,313.337 ; 752.389,315.503 ccw(c755.152,315.503) 753.198,313.549 ; v1@752.756,324.799 ccw(c752.414,324.457) 752.414,324.94 ccw(c752.414,325.423) v1@752.756,325.081 ; v1(752.897,324.94) 748.706,324.94 748.452,325.194 ; v1@753.078,319.606 cw(c752.595,319.606) 752.937,319.265 cw(c753.278,318.923) v1@753.278,319.406 ; v1(753.278,319.606) 752.389,318.717 752.389,313.51 752.774,313.125 ; 546.481,343.99 ccw(c546.218,343.99) 546.367,344.206 cw(c546.218,343.99) 546.481,343.99 ; 546.481,343.99 cw(c546.744,343.99) 546.595,344.206 ccw(c546.744,343.99) 546.481,343.99 ; 567.777,305.723 568.198,306.144 587.375,306.144 587.777,305.742 ; 606.552,325.194 ccw(c606.289,325.194) 606.438,325.41 cw(c606.289,325.194) 606.552,325.194 ; 606.552,325.194 cw(c606.815,325.194) 606.666,325.41 ccw(c606.815,325.194) 606.552,325.194 ; 688.381,343.99 ccw(c688.118,343.99) 688.267,344.206 cw(c688.118,343.99) 688.381,343.99 ; 688.381,343.99 cw(c688.644,343.99) 688.495,344.206 ccw(c688.644,343.99) 688.381,343.99 ; 709.677,305.723 710.098,306.144 729.275,306.144 729.677,305.742 ; 748.452,325.194 ccw(c748.189,325.194) 748.338,325.41 cw(c748.189,325.194) 748.452,325.194 ; 748.452,325.194 cw(c748.715,325.194) 748.566,325.41 ccw(c748.715,325.194) 748.452,325.194
  Bottom Layer w0.45: 527.09,303.604 527.09,307.835 528.066,308.811 551.18,308.811 551.688,309.319 v1(551.688,313.002) ; 532.09,303.604 532.09,307.12 532.511,307.541 551.942,307.541 552.577,308.176 v1@552.577,313.637 ; v1(540.258,339.418) v1(545.211,339.418) ; v1(541.401,340.84) v1(569.341,340.84) v1@576.961,340.84 ; v1(543.941,344.371) 543.941,343.355 544.449,342.847 v1(578.993,342.847) ; 547.777,303.604 547.777,303.07 549.402,301.445 553.974,301.445 554.863,302.334 554.863,312.367 554.482,312.748 v1(554.482,313.51) ; 548.658,340.84 cw(c548.658,340.452) v1@548.933,340.727 ; v1@549.109,340.727 cw(c549.384,340.452) 549.384,340.84 ; v1(550.291,339.418) v1(568.325,339.418) v1(573.151,339.418) ; 552.777,303.604 552.777,306.725 553.593,307.541 v1(553.593,313.002) ; 559.707,340.84 cw(c559.707,340.452) v1@559.982,340.727 ; v1@560.158,340.727 cw(c560.433,340.452) 560.433,340.84 ; v1(560.705,323.416) v1(560.705,337.132) ; v1(566.417,312.243) v1(584.711,312.243) ; 568.901,349.659 cw(c568.261,349.019) 569.166,349.019 cw(c570.071,349.019) 569.431,349.659 ; 569.166,350.086 569.166,346.959 569.849,346.276 582.041,346.276 582.676,345.641 v1(582.676,343.101) ; 569.166,352.626 569.595,352.626 570.484,351.737 570.484,347.8 571.3,346.984 582.857,346.984 583.565,346.276 v1@583.565,342.72 ; 569.171,352.539 cw(c569.237,351.473) 569.993,352.228 ; 569.199,352.09 cw(c569.319,350.144) 570.698,351.523 ; 571.706,352.089 cw(c571.706,350.063) 573.138,351.496 ; 571.706,352.626 572.008,352.626 573.024,351.61 573.024,348.943 574.04,347.927 583.819,347.927 584.581,347.165 v1(584.581,343.101) ; 572.243,352.626 ccw(c572.81,352.626) 572.409,352.225 ; 576.598,340.84 cw(c576.598,340.452) v1@576.873,340.727 ; 583.565,343.175 ccw(c584.084,343.175) v1@583.717,342.808 ; 668.99,303.604 668.99,307.835 669.966,308.811 693.08,308.811 693.588,309.319 v1(693.588,313.002) ; 673.99,303.604 673.99,307.12 674.411,307.541 693.842,307.541 694.477,308.176 v1@694.477,313.637 ; v1(682.158,339.418) v1(687.111,339.418) ; v1(683.301,340.84) v1(711.241,340.84) v1@718.861,340.84 ; v1(685.841,344.371) 685.841,343.355 686.349,342.847 v1(720.893,342.847) ; 689.677,303.604 689.677,303.07 691.302,301.445 695.874,301.445 696.763,302.334 696.763,312.367 696.382,312.748 v1(696.382,313.51) ; 690.558,340.84 cw(c690.558,340.452) v1@690.833,340.727 ; v1@691.009,340.727 cw(c691.284,340.452) 691.284,340.84 ; v1(692.191,339.418) v1(710.225,339.418) v1(715.051,339.418) ; 694.677,303.604 694.677,306.725 695.493,307.541 v1(695.493,313.002) ; 701.607,340.84 cw(c701.607,340.452) v1@701.882,340.727 ; v1@702.058,340.727 cw(c702.333,340.452) 702.333,340.84 ; v1(702.605,323.416) v1(702.605,337.132) ; v1(708.317,312.243) v1(726.611,312.243) ; 710.801,349.659 cw(c710.161,349.019) 711.066,349.019 cw(c711.971,349.019) 711.331,349.659 ; 711.066,350.086 711.066,346.959 711.749,346.276 723.941,346.276 724.576,345.641 v1(724.576,343.101) ; 711.066,352.626 711.495,352.626 712.384,351.737 712.384,347.8 713.2,346.984 724.757,346.984 725.465,346.276 v1@725.465,342.72 ; 711.071,352.539 cw(c711.137,351.473) 711.893,352.228 ; 711.099,352.09 cw(c711.219,350.144) 712.598,351.523 ; 713.606,352.089 cw(c713.606,350.063) 715.038,351.496 ; 713.606,352.626 713.908,352.626 714.924,351.61 714.924,348.943 715.94,347.927 725.719,347.927 726.481,347.165 v1(726.481,343.101) ; 714.143,352.626 ccw(c714.71,352.626) 714.309,352.225 ; 718.498,340.84 cw(c718.498,340.452) v1@718.773,340.727 ; 725.465,343.175 ccw(c725.984,343.175) v1@725.617,342.808
  Bottom Layer w0.65: 530.987,351.536 530.987,354.711 531.95,355.674 572.262,355.674 572.77,355.166 ; 531.622,351.663 531.622,354.584 532.204,355.166 572.135,355.166 ; 572.35,355.166 cw(c572.35,354.238) v1@573.006,354.894 ; 572.532,355.404 cw(c571.406,354.277) v1@572.999,354.277 ; v1(581.406,340.815) 598.424,340.815 ; v1(581.787,339.418) 597.281,339.418 ; v1(595.63,395.552) v1(610.043,395.552) ; 598.624,338.075 597.281,339.418 ; 599.528,324.979 600.71,323.797 ; 599.528,339.711 598.424,340.815 ; 599.603,322.527 cw(c599.603,321.166) v1@600.565,322.128 ; v1@600.601,322.128 cw(c601.563,321.166) 601.563,322.527 ; 600.813,322.527 cw(c600.813,321.166) v1@601.775,322.128 ; v1@601.811,322.128 cw(c602.773,321.166) 602.773,322.527 ; v1(606.298,420.444) 606.425,420.317 v1(613.286,420.317) ; v1@606.316,420.462 ccw(c606.665,420.811) 606.665,420.317 ; v1@606.809,420.955 ccw(c608.349,422.495) 608.349,420.317 ; v1(608.33,389.71) 608.33,393.139 608.33,394.028 608.838,394.536 609.346,394.536 ; 608.33,393.52 609.346,394.536 ; v1(609.6,389.71) 609.6,393.139 ; v1(610.489,322.527) v1(606.806,322.527) 599.186,322.527 598.624,323.089 598.624,338.837 598.043,339.418 597.281,339.418 ; v1(610.489,323.797) 600.71,323.797 ; v1@616.098,400.689 ccw(c614.977,401.81) 616.563,401.81 ; v1@616.118,400.696 ccw(c616.194,401.785) 616.966,401.013 ; v1@616.545,404.297 cw(c615.53,403.282) 616.966,403.282 ; 616.563,403.79 cw(c617.999,403.79) v1@616.984,404.805 ; v1@616.563,404.175 cw(c617.243,404.175) v1@616.976,404.8 ; 617.474,394.536 v1(618.744,395.806) v1(618.744,395.044) 618.236,394.536 609.346,394.536 ; 672.887,351.536 672.887,354.711 673.85,355.674 714.162,355.674 714.67,355.166 ; 673.522,351.663 673.522,354.584 674.104,355.166 714.035,355.166 ; 714.25,355.166 cw(c714.25,354.238) v1@714.906,354.894 ; 714.432,355.404 cw(c713.306,354.277) v1@714.899,354.277 ; v1(723.306,340.815) 740.324,340.815 ; v1(723.687,339.418) 739.181,339.418 ; v1(737.53,395.552) v1(751.943,395.552) ; 740.524,338.075 739.181,339.418 ; 741.428,324.979 742.61,323.797 ; 741.428,339.711 740.324,340.815 ; 741.503,322.527 cw(c741.503,321.166) v1@742.465,322.128 ; v1@742.501,322.128 cw(c743.463,321.166) 743.463,322.527 ; 742.713,322.527 cw(c742.713,321.166) v1@743.675,322.128 ; v1@743.711,322.128 cw(c744.673,321.166) 744.673,322.527 ; v1(748.198,420.444) 748.325,420.317 v1(755.186,420.317) ; v1@748.216,420.462 ccw(c748.565,420.811) 748.565,420.317 ; v1@748.709,420.955 ccw(c750.249,422.495) 750.249,420.317 ; v1(750.23,389.71) 750.23,393.139 750.23,394.028 750.738,394.536 751.246,394.536 ; 750.23,393.52 751.246,394.536 ; v1(751.5,389.71) 751.5,393.139 ; v1(752.389,322.527) v1(748.706,322.527) 741.086,322.527 740.524,323.089 740.524,338.837 739.943,339.418 739.181,339.418 ; v1(752.389,323.797) 742.61,323.797 ; v1@757.998,400.689 ccw(c756.877,401.81) 758.463,401.81 ; v1@758.018,400.696 ccw(c758.094,401.785) 758.866,401.013 ; v1@758.445,404.297 cw(c757.43,403.282) 758.866,403.282 ; 758.463,403.79 cw(c759.899,403.79) v1@758.884,404.805 ; v1@758.463,404.175 cw(c759.143,404.175) v1@758.876,404.8 ; 759.374,394.536 v1(760.644,395.806) v1(760.644,395.044) 760.136,394.536 751.246,394.536 ; 572.135,355.166 v1(573.024,354.277) v1(573.024,354.912) 572.77,355.166 ; 572.135,355.166 572.77,355.166 ; 598.424,340.815 598.932,340.815 599.528,340.219 599.528,324.344 600.075,323.797 600.71,323.797 ; 616.966,401.013 616.624,400.671 v1(616.116,400.671) 616.563,401.118 v1(616.563,404.315) 616.966,404.718 v1(616.966,404.823) ; 616.966,401.013 v1(616.966,404.823) ; v1(616.966,404.823) cw(c616.476,404.823) 616.559,404.34 ccw(c616.476,404.823) v1(616.966,404.823) ; 714.035,355.166 v1(714.924,354.277) v1(714.924,354.912) 714.67,355.166 ; 714.035,355.166 714.67,355.166 ; 740.324,340.815 740.832,340.815 741.428,340.219 741.428,324.344 741.975,323.797 742.61,323.797 ; 758.866,401.013 758.524,400.671 v1(758.016,400.671) 758.463,401.118 v1(758.463,404.315) 758.866,404.718 v1(758.866,404.823) ; 758.866,401.013 v1(758.866,404.823) ; v1(758.866,404.823) cw(c758.376,404.823) 758.459,404.34 ccw(c758.376,404.823) v1(758.866,404.823)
